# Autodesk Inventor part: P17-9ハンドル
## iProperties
Created: 2008-07
Part Number: P17-9ハンドル
Document SubType Name: Modeling
Designer: y-shimohigashi
Density: 1 g/cm^3
Stock Number: P17-9ハンドル
Author: y-shimohigashi
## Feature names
1. 回転1 [Revolution]
